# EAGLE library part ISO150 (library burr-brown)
Dual, Isolated, Bi-Directional Digital Coupler
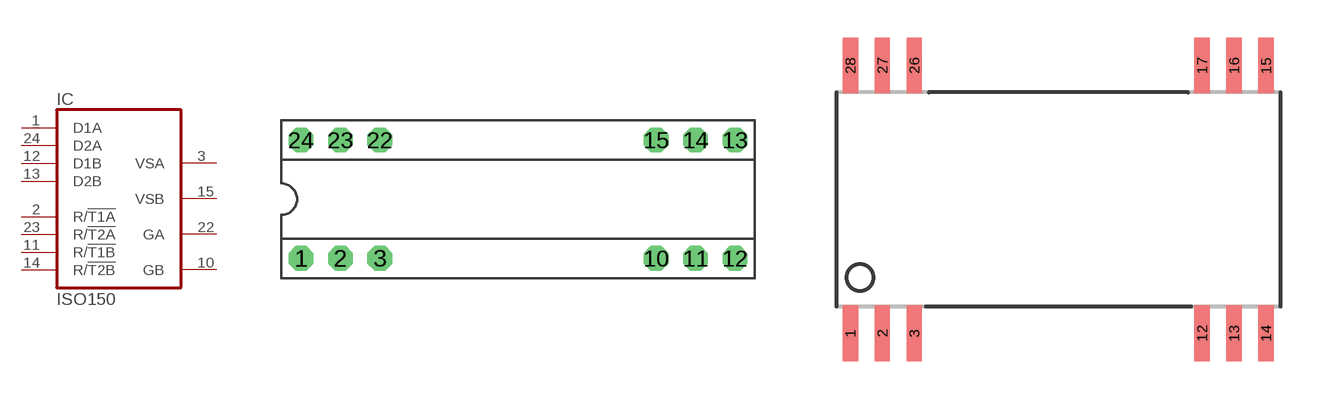
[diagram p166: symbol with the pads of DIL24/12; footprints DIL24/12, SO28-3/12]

Designator prefix IC

## ISO150P (OC_FARNELL: unknown; OC_NEWARK: unknown)  [DIL24/12]
1  D1A
2  R/!T1A  in
3  VSA  pwr
10  GB  pwr
11  R/!T1B  in
12  D1B
13  D2B
14  R/!T2B  in
15  VSB  pwr
22  GA  pwr
23  R/!T2A  in
24  D2A

## ISO150U (MF: TEXAS INSTRUMENTS; MPN: ISO150AUG4; OC_FARNELL: 1206917; OC_NEWARK: 40K6952)  [SO28-3/12]
1  D1A
2  R/!T1A  in
3  VSA  pwr
12  GB  pwr
13  R/!T1B  in
14  D1B
15  D2B
16  R/!T2B  in
17  VSB  pwr
26  GA  pwr
27  R/!T2A  in
28  D2A

## Footprint DIL24/12 (pad centres in mm)
Dual In Line
drill 0.813 pad 1.6 octagon: 1 -13.97,-3.81; 2 -11.43,-3.81; 3 -8.89,-3.81; 10 8.89,-3.81; 11 11.43,-3.81; 12 13.97,-3.81; 13 13.97,3.81; 14 11.43,3.81; 15 8.89,3.81; 22 -8.89,3.81; 23 -11.43,3.81; 24 -13.97,3.81

## Footprint SO28-3/12 (pad centres in mm)
Small Outline Package
smd 0.61 x 2.21: 1 -8.255,-5.315; 2 -6.985,-5.315; 3 -5.715,-5.315; 12 5.715,-5.315; 13 6.985,-5.315; 14 8.255,-5.315; 15 8.255,5.315; 16 6.985,5.315; 17 5.715,5.315; 26 -5.715,5.315; 27 -6.985,5.315; 28 -8.255,5.315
